(* Logix 5000 project; controller RLX2_AOI 1756-L63 rev 16.7; software revision 16.04 *)

TASK MainTask (continuous, watchdog 500 ms) : MainProgram

MODULES
   Local : 1756-L63 (ICP 0, rev 16.7)
      ENBT : 1756-ENBT (ICP 1, Ethernet 192.168.0.254, rev 4.1)
         RLX2 : vendor 1 type 0 code 23 (Ethernet 192.168.0.250, rev 1.1)
END_MODULES

TYPE RLX2_CONTROL :   // Contains trigger bit for the functions supported by the RLX2. Bit should be set as 1 to trigger AOI request
STRUCT
   GetStatusData : BOOL;   // Reads Diagnostic status data from RLX2
   GetCRCSignature : BOOL;   // Read CRC File Signature Information
END_STRUCT
END_TYPE

TYPE RLX2_CRC :   // CRC File Signature Information
STRUCT
   OS_Sig : DINT;   // CRC signature of OS related files
   Wireless_Sig : DINT;   // CRC signature of Wireless related files
   Config_Sig : DINT;   // CRC signature of Configuration related files
   Security_Sig : DINT;   // CRC signature of Security related files
   Web_Sig : DINT;   // CRC signature of the web pages image file.
   SDCard_Sig : DINT;   // CRC signature of the contents of the SD Card
   Reserved1 : DINT;   // Reserved
   Reserved2 : DINT;   // Reserved
   Reserved3 : DINT;   // Reserved
   Reserved4 : DINT;   // Reserved
   Reserved5 : DINT;   // Reserved
   Reserved6 : DINT;   // Reserved
   Reserved7 : DINT;   // Reserved
   Reserved8 : DINT;   // Reserved
   Reserved9 : DINT;   // Reserved
   Reserved10 : DINT;   // Reserved
   Reserved11 : DINT;   // Reserved
   Reserved12 : DINT;   // Reserved
   Reserved13 : DINT;   // Reserved
   Reserved14 : DINT;   // Reserved
END_STRUCT
END_TYPE

TYPE RLX2_LINKTIME :   // RLX2 Repeater Link Time
STRUCT
   Days : DINT;   // Number of Days Repeater has been connected with a Master
   Hours : DINT;   // Number of Hours Repeater has been connected with a Master
   Minutes : DINT;   // Number of Minutes Repeater has been connected with a Master
   Seconds : DINT;   // Number of Seconds Repeater has been connected with a Master
END_STRUCT
END_TYPE

TYPE RLX2_ModuleDef :   // Main RLX2 Radio definition
STRUCT
   CONTROL : RLX2_CONTROL;   // Trigger bits used to request functions from RLX2 Radio
   STATUS : RLX2_STATUS;   // RLX2 radio diagnostic data
   CRC : RLX2_CRC;   // RLX2 CRC file signature Information
   UTIL : RLX2_UTIL;   // *Do Not Modify*
END_STRUCT
END_TYPE

TYPE RLX2_STATUS :   // RLX2 Radio Status Data
STRUCT
   SSID : SINT[32];   // The Service Set Identifier is a name assigned to the wireless network
   IPAddress : INT[4];   // Radio's IP address
   MACAddress : SINT[6];   // Physical Media Access Control (MAC) address of the device
   NetworkMode : SINT;   // RLX2 radio Network mode (Master= 6 Repeater=7 Client=1)
   ConnectionState : SINT;   // Connection State of Radio
   SignalStrength : INT;   // Current Strength of the signal in dBm
   Channel : INT;   // Current Channel in which RLX2 is transmitting
   WEP : SINT;   // WEP encryption key
   Flags : DINT;   // Flags: Flag[0/1]= Extension channel Flag[2]= SSIDhidden Flag[3]=Allow Children Flag[4/5]=STP/RSTP Flag[6]=TXusingGI
   MasterMACAddress : SINT[6];   // MAC Address of Parent Radio in which Repeater or Client is linked
   HopCount : SINT;   // Number of hops to the master
   PortStatus : SINT;   // Ethernet Port Status (Speed 1=10Mb/s 2=100Mb/s 3=1000Mb/s)
   Associations : INT;   // Number of network elements to which radio has wireless connection
   BridgeAssociations : INT;   // Number of devices to which radio has wireless connection
   TxRadioThroughput : DINT;   // Transmit throughput in kilobits per second
   RxRadioThroughput : DINT;   // Receive throughput in kilobits per second
   Uptime : RLX2_UPTIME;   // This is the amount of time the radio has been running since power up (Days/Hours/Minutes/Seconds)
   LinkTime : RLX2_LINKTIME;   // The time the radio has been linked (Days/Hours/Minutes/Seconds)
   TxPacketRate : DINT;   // Total number of packets transmitted
   RxPacketRate : DINT;   // Total number of packets received
   ModuleName : SINT[32];   // The name of the radio
   ProductName : SINT[32];   // Name of product family
   ImageVerStr : SINT[28];   // Firmware version loaded in device
   TxGood : DINT;   // Number of Good Transmitted Frames
   RxGood : DINT;   // Number of Good Received Frames
   TxBad : DINT;   // Number of Bad Transmitted Frames
   RxBad : DINT;   // Number of Bad Received Frames
   TxDirectedFrames : DINT;   // Number of Transmitted Directed Frames
   TxMulticastFrames : DINT;   // Number of Transmitted Multicast Frames
   TxBroadcastFrames : DINT;   // Number of Transmitted Broadcast Frames
   RxDirectedFrames : DINT;   // Number of Received Directed Frames
   RxMulticastFrames : DINT;   // Number of Received Multicast Frames
   RxBroadcastFrames : DINT;   // Number of Received Broadcast Frames
   RxCRCErr : DINT;   // Number of CRC Errors
   Retries : SINT;   // Percentage retransmission (0-100%)
   Utilization : SINT;   // Measured channel utilization (0-100%)
   ChannelWidth : SINT;   // Configured channel width (20 or 40 MHz)
   Antennas : SINT;   // Active Antenna Information
   TxRate : INT;   // Encoded Current Tx Rate to Parent (Client/Repeater Only)
   TxBitRate : INT;   // Actual Tx Bit Rate to Parent in 100 kb/s units
   TxBcastRate : INT;   // Broadcast packet rate being sent to radio (pps)
   TxMcstRate : INT;   // Multicast packet rate being sent to radio (pps)
   Reserved1 : DINT;   // Reserved
   Reserved2 : DINT;   // Reserved
   Reserved3 : DINT;   // Reserved
   Reserved4 : DINT;   // Reserved
   Reserved5 : DINT;   // Reserved
   Reserved6 : DINT;   // Reserved
   Reserved7 : DINT;   // Reserved
   Reserved8 : DINT;   // Reserved
   Reserved9 : DINT;   // Reserved
   Reserved10 : DINT;   // Reserved
   Reserved11 : DINT;   // Reserved
   Reserved12 : DINT;   // Reserved
   Reserved13 : DINT;   // Reserved
   Reserved14 : DINT;   // Reserved
   Reserved15 : DINT;   // Reserved
   Reserved16 : DINT;   // Reserved
END_STRUCT
END_TYPE

TYPE RLX2_UPTIME :
STRUCT
   Days : DINT;
   Hours : DINT;
   Minutes : DINT;
   Seconds : DINT;
END_STRUCT
END_TYPE

TYPE RLX2_UTIL :   // Internal tag used for internal ladder processing. Not to be updated by user application
STRUCT
   ImgVersionInformation : SINT[28];   // *Do Not Modify*
   RadioInformation : SINT[296];   // *Do Not Modify*
   CRCInformation : DINT[20];   // *Do Not Modify*
   TotalupTime : DINT;   // *Do Not Modify*
   TotalLinkTime : DINT;   // *Do Not Modify*
END_STRUCT
END_TYPE

ADD_ON_INSTRUCTION AOI_RLX2   (* revision 2.0, ExecutePrescan *)
// Add-On Instruction for RLX2 Industrial Hotspot
// Revision note:
// 2.0 -- Added Support for Extended Status and CRC File Information (v38)
// Help:
// 1.5 - Fix to Logic to display correct RSSI
// 1.4 --  Change the display information for the Link and Uptime of the radio
VAR_IN_OUT
   RLX2 : RLX2_ModuleDef; {required}
   RLX2_MSG_GET_IMG_VER : MESSAGE; {required}
   RLX2_MSG_GET_STATUS : MESSAGE; {required}
   RLX2_MSG_GET_CRC_SIG : MESSAGE; {required}
END_VAR
VAR
   Hold64 : INT[2];
   HoldRSSI : INT;
   Hold66 : INT[2];
   ImgVersion : DINT;
   TriggerStatusMSG : BOOL;   // Trigger Status Information MSG
END_VAR

ROUTINE Logic   (* ladder *)
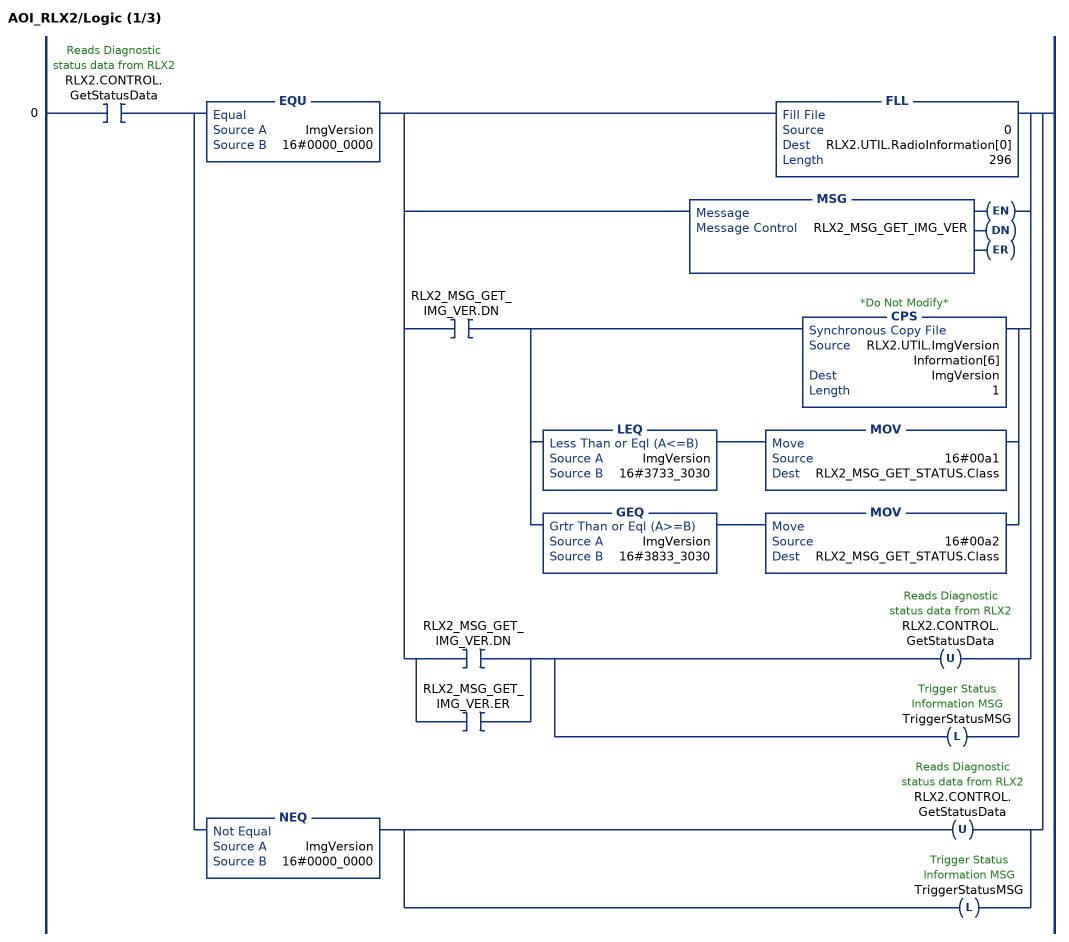
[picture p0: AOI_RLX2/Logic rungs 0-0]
   0: XIC(RLX2.CONTROL.GetStatusData)[EQU(ImgVersion,16#0000_0000) [FLL(0,RLX2.UTIL.RadioInformation[0],296) ,MSG(RLX2_MSG_GET_IMG_VER) ,[XIC(RLX2_MSG_GET_IMG_VER.DN) [CPS(RLX2.UTIL.ImgVersionInformation[6],ImgVersion,1) ,LEQ(ImgVersion,16#3733_3030) MOV(16#00a1,RLX2_MSG_GET_STATUS.Class) ,GEQ(ImgVersion,16#3833_3030) MOV(16#00a2,RLX2_MSG_GET_STATUS.Class) ] ,[XIC(RLX2_MSG_GET_IMG_VER.DN) ,XIC(RLX2_MSG_GET_IMG_VER.ER) ] [OTU(RLX2.CONTROL.GetStatusData) ,OTL(TriggerStatusMSG) ] ] ] ,NEQ(ImgVersion,16#0000_0000) [OTU(RLX2.CONTROL.GetStatusData) ,OTL(TriggerStatusMSG) ] ];
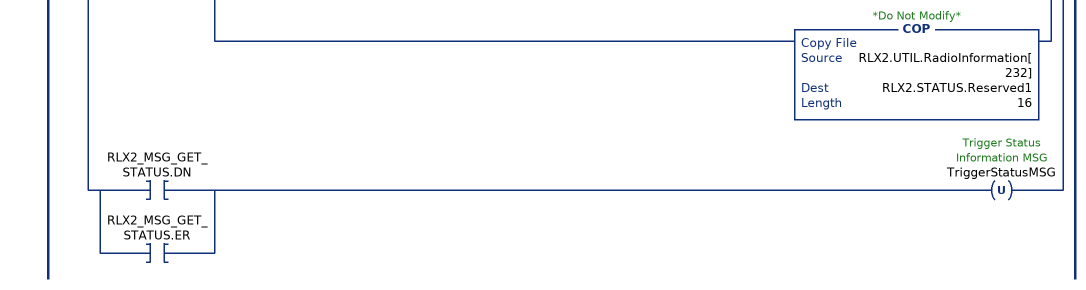
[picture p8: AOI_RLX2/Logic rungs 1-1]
   1: XIC(TriggerStatusMSG)[MSG(RLX2_MSG_GET_STATUS) ,[XIC(RLX2_MSG_GET_STATUS.DN) [COP(RLX2.UTIL.RadioInformation[0],RLX2.STATUS.SSID[0],32) ,MVM(RLX2.UTIL.RadioInformation[32],255,RLX2.STATUS.IPAddress[0]) ,MVM(RLX2.UTIL.RadioInformation[33],255,RLX2.STATUS.IPAddress[1]) ,MVM(RLX2.UTIL.RadioInformation[34],255,RLX2.STATUS.IPAddress[2]) ,MVM(RLX2.UTIL.RadioInformation[35],255,RLX2.STATUS.IPAddress[3]) ,COP(RLX2.UTIL.RadioInformation[36],RLX2.STATUS.MACAddress[0],6) ,COP(RLX2.UTIL.RadioInformation[42],RLX2.STATUS.NetworkMode,1) ,COP(RLX2.UTIL.RadioInformation[43],RLX2.STATUS.ConnectionState,1) ,NEQ(RLX2.STATUS.NetworkMode,6) COP(RLX2.UTIL.RadioInformation[44],HoldRSSI,1) SUB(HoldRSSI,100,RLX2.STATUS.SignalStrength) ,MVM(RLX2.UTIL.RadioInformation[46],255,RLX2.STATUS.Channel) ,COP(RLX2.UTIL.RadioInformation[47],RLX2.STATUS.WEP,1) ,COP(RLX2.UTIL.RadioInformation[48],RLX2.STATUS.Flags,4) ,COP(RLX2.UTIL.RadioInformation[52],RLX2.STATUS.MasterMACAddress[0],6) ,COP(RLX2.UTIL.RadioInformation[58],RLX2.STATUS.HopCount,1) ,COP(RLX2.UTIL.RadioInformation[59],RLX2.STATUS.PortStatus,1) ,COP(RLX2.UTIL.RadioInformation[60],RLX2.STATUS.Associations,2) ,COP(RLX2.UTIL.RadioInformation[62],RLX2.STATUS.BridgeAssociations,2) ,COP(RLX2.UTIL.RadioInformation[64],Hold64[0],1) COP(Hold64[0],RLX2.STATUS.TxRadioThroughput,1) ,COP(RLX2.UTIL.RadioInformation[66],Hold66[0],1) COP(Hold66[0],RLX2.STATUS.RxRadioThroughput,1) ,[COP(RLX2.UTIL.RadioInformation[68],RLX2.UTIL.TotalupTime,4) ,CPT(RLX2.STATUS.Uptime.Days,(RLX2.UTIL.TotalupTime/60/60/24)) ,CPT(RLX2.STATUS.Uptime.Hours,(RLX2.UTIL.TotalupTime/60/60)-(RLX2.STATUS.Uptime.Days*24)) ,CPT(RLX2.STATUS.Uptime.Minutes,(RLX2.UTIL.TotalupTime/60)-(RLX2.STATUS.Uptime.Days*24*60)-(RLX2.STATUS.Uptime.Hours*60)) ,CPT(RLX2.STATUS.Uptime.Seconds,(RLX2.UTIL.TotalupTime)-(RLX2.STATUS.Uptime.Days*24*60*60)-(RLX2.STATUS.Uptime.Hours*60*60)-(RLX2.STATUS.Uptime.Minutes*60)) ] ,[COP(RLX2.UTIL.RadioInformation[72],RLX2.UTIL.TotalLinkTime,4) ,CPT(RLX2.STATUS.LinkTime.Days,(RLX2.UTIL.TotalLinkTime/60/60/24)) ,CPT(RLX2.STATUS.LinkTime.Hours,(RLX2.UTIL.TotalLinkTime/60/60)-(RLX2.STATUS.LinkTime.Days*24)) ,CPT(RLX2.STATUS.LinkTime.Minutes,(RLX2.UTIL.TotalLinkTime/60)-(RLX2.STATUS.LinkTime.Days*24*60)-(RLX2.STATUS.LinkTime.Hours*60)) ,CPT(RLX2.STATUS.LinkTime.Seconds,(RLX2.UTIL.TotalLinkTime)-(RLX2.STATUS.LinkTime.Days*24*60*60)-(RLX2.STATUS.LinkTime.Hours*60*60)-(RLX2.STATUS.LinkTime.Minutes*60)) ] ,COP(RLX2.UTIL.RadioInformation[76],RLX2.STATUS.TxPacketRate,4) ,COP(RLX2.UTIL.RadioInformation[80],RLX2.STATUS.RxPacketRate,4) ,COP(RLX2.UTIL.RadioInformation[84],RLX2.STATUS.ModuleName[0],32) ,COP(RLX2.UTIL.RadioInformation[116],RLX2.STATUS.ProductName[0],32) ,COP(RLX2.UTIL.RadioInformation[148],RLX2.STATUS.ImageVerStr[0],28) ,COP(RLX2.UTIL.RadioInformation[176],RLX2.STATUS.TxGood,4) ,COP(RLX2.UTIL.RadioInformation[180],RLX2.STATUS.RxGood,4) ,COP(RLX2.UTIL.RadioInformation[184],RLX2.STATUS.TxBad,4) ,COP(RLX2.UTIL.RadioInformation[188],RLX2.STATUS.RxBad,4) ,COP(RLX2.UTIL.RadioInformation[192],RLX2.STATUS.TxDirectedFrames,4) ,COP(RLX2.UTIL.RadioInformation[196],RLX2.STATUS.TxMulticastFrames,4) ,COP(RLX2.UTIL.RadioInformation[200],RLX2.STATUS.TxBroadcastFrames,4) ,COP(RLX2.UTIL.RadioInformation[204],RLX2.STATUS.RxDirectedFrames,4) ,COP(RLX2.UTIL.RadioInformation[208],RLX2.STATUS.RxMulticastFrames,4) ,COP(RLX2.UTIL.RadioInformation[212],RLX2.STATUS.RxBroadcastFrames,4) ,COP(RLX2.UTIL.RadioInformation[216],RLX2.STATUS.RxCRCErr,4) ,COP(RLX2.UTIL.RadioInformation[220],RLX2.STATUS.Retries,1) ,COP(RLX2.UTIL.RadioInformation[221],RLX2.STATUS.Utilization,1) ,COP(RLX2.UTIL.RadioInformation[222],RLX2.STATUS.ChannelWidth,1) ,COP(RLX2.UTIL.RadioInformation[223],RLX2.STATUS.Antennas,1) ,COP(RLX2.UTIL.RadioInformation[224],RLX2.STATUS.TxRate,1) ,COP(RLX2.UTIL.RadioInformation[226],RLX2.STATUS.TxBitRate,1) ,COP(RLX2.UTIL.RadioInformation[228],RLX2.STATUS.TxBcastRate,1) ,COP(RLX2.UTIL.RadioInformation[230],RLX2.STATUS.TxMcstRate,1) ,COP(RLX2.UTIL.RadioInformation[232],RLX2.STATUS.Reserved1,16) ] ,[XIC(RLX2_MSG_GET_STATUS.DN) ,XIC(RLX2_MSG_GET_STATUS.ER) ] OTU(TriggerStatusMSG) ] ];
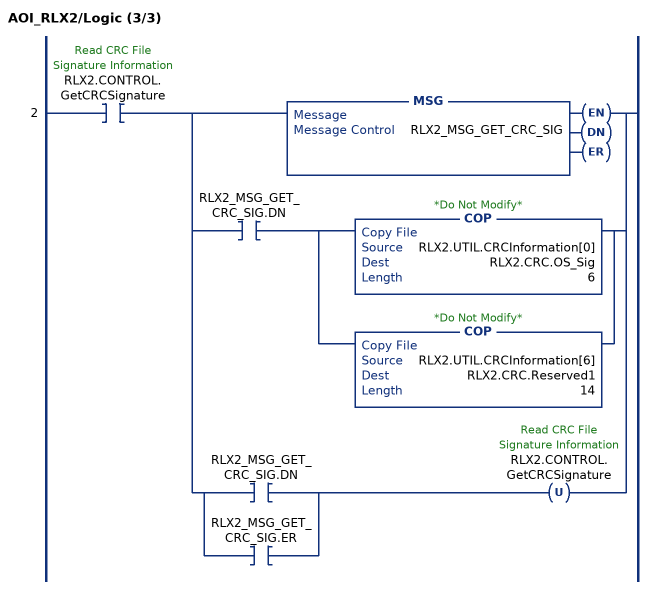
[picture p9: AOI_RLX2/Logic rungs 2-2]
   2: XIC(RLX2.CONTROL.GetCRCSignature)[MSG(RLX2_MSG_GET_CRC_SIG) ,[XIC(RLX2_MSG_GET_CRC_SIG.DN) [COP(RLX2.UTIL.CRCInformation[0],RLX2.CRC.OS_Sig,6) ,COP(RLX2.UTIL.CRCInformation[6],RLX2.CRC.Reserved1,14) ] ,[XIC(RLX2_MSG_GET_CRC_SIG.DN) ,XIC(RLX2_MSG_GET_CRC_SIG.ER) ] OTU(RLX2.CONTROL.GetCRCSignature) ] ];
END_ROUTINE

ROUTINE Prescan   (* ladder *)
// Reset ImgVersion on PLC transitions from PROGRAM -> RUN mode or powers up
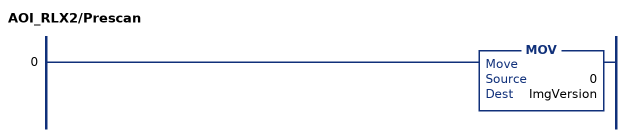
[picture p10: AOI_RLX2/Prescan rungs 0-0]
   0: MOV(0,ImgVersion);
END_ROUTINE
END_ADD_ON_INSTRUCTION

VAR_GLOBAL   (* controller tags *)
   AOI_RLX2 : AOI_RLX2;
   RLX2 : RLX2_ModuleDef;
   RLX2_MSGgetCRC : MESSAGE;
        MessageParameters(ServiceCode := 16#0001, LocalElement := RLX2.UTIL.CRCInformation[0], DestinationTag := RLX2.UTIL.CRCInformation[0], ...)
   RLX2_MSGgetImgVers : MESSAGE;
        MessageParameters(ServiceCode := 16#000e, DestinationTag := RLX2.UTIL.ImgVersionInformation, ...)
   RLX2_MSGgetStatus : MESSAGE;
        MessageParameters(ServiceCode := 16#0001, LocalElement := RLX2.UTIL.RadioInformation[0], DestinationTag := RLX2.UTIL.RadioInformation[0], ...)
END_VAR

PROGRAM MainProgram   (* main routine MainRoutine *)

ROUTINE MainRoutine   (* ladder *)
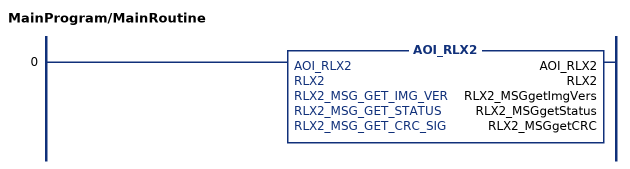
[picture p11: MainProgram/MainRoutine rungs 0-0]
   0: AOI_RLX2(AOI_RLX2,RLX2,RLX2_MSGgetImgVers,RLX2_MSGgetStatus,RLX2_MSGgetCRC);
END_ROUTINE
END_PROGRAM
